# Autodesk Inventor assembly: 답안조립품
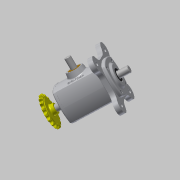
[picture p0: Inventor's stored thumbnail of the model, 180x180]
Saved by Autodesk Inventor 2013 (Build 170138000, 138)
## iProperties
Created: 2016-05
Part Number: 답안조립품
Document SubType Name: Assembly
Designer: Administrator
Author: Administrator
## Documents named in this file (11)
- C:\Users\Administrator\Desktop\460507V1012\답안조립품.iam
- C:\Users\Administrator\Desktop\460507V1012\M4x0.7x12.ipt
- C:\Users\Administrator\Desktop\460507V1012\베어링-6203.ipt
- C:\Users\Administrator\Desktop\460507V1012\본체.ipt
- C:\Users\Administrator\Desktop\460507V1012\부시.ipt
- C:\Users\Administrator\Desktop\460507V1012\스프로킷.ipt
- C:\Users\Administrator\Desktop\460507V1012\슬라이더.ipt
- C:\Users\Administrator\Desktop\460507V1012\오일실.ipt
- C:\Users\Administrator\Desktop\460507V1012\커버.ipt
- C:\Users\Administrator\Desktop\460507V1012\키5x5.ipt
- C:\Users\Administrator\Desktop\460507V1012\편심축.ipt
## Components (8 placed, 1 different names)
1. M4x0.7x12:1
2. M4x0.7x12:2
3. M4x0.7x12:3
4. M4x0.7x12:4
5. M4x0.7x12:5
6. M4x0.7x12:6
7. M4x0.7x12:7
8. M4x0.7x12:8
